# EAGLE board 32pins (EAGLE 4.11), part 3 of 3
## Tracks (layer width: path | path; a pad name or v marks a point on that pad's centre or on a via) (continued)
PUC1\ (continued)
  Top 0.254: SV4.6 184.78,32.86 180.97,32.86 179.7,34.12 167.63,34.12 167,34.76 152.4,34.76 151.12,33.49 151.12,31.59 Q38.G
  Bottom 0.254: Q38.G 151.76,30.95 152.4,30.95 154.3,29.05 155.57,29.05 156.84,27.78 D70.C
PUD1\
  Top 0.254: Q40.G 131.44,30.95 132.08,30.95 133.34,29.68 133.34,27.14 133.98,26.51 135.25,26.51 136.52,27.78 D72.C
  Bottom 0.254: SV4.8 186.05,35.4 187.32,34.12 188.59,34.12 190.5,32.22 190.5,25.87 177.16,12.54 172.08,12.54 170.81,11.27 170.81,8.73 168.91,6.82 130.81,6.82 127,10.63 127,27.14 126.36,27.78 129.53,30.95 130.17,30.95 Q40.G
PUD2\  (via drill 0.61)
  Top 0.254: v144.78,79.84 v140.97,79.84 | D100.C 147.31,71.59 148.59,72.86 148.59,75.4 v146.68,77.3 v151.12,77.3 | v153.66,78.57 178.43,78.57 179.7,79.84 179.7,82.38 185.41,88.1 SV2.4
  Bottom 0.254: v140.97,79.84 140.97,74.77 Q68.G | v144.78,79.84 144.78,79.21 144.14,78.57 145.41,77.3 v146.68,77.3 | v153.66,78.57 152.4,77.3 v151.12,77.3
PUE1\
  Bottom 0.254: Q42.G 161.92,15.71 162.56,15.71 164.46,13.81 165.73,13.81 167,12.54 D74.C 167.63,13.17 168.91,14.44 168.91,16.98 177.8,25.87 185.41,25.87 187.32,27.78 SV4.1
PUE2\
  Top 0.254: Q70.G 131.44,89.37 132.08,89.37 133.34,88.1 133.34,85.56 133.98,84.92 135.25,84.92 136.52,86.19 D102.C 137.79,86.19 139.06,86.19 140.97,84.29 140.97,83.02 141.6,82.38 149.86,82.38 150.49,81.75 166.37,81.75 167,82.38 177.16,82.38 185.41,90.64 SV2.6
PUF1\
  Top 0.254: Q44.G 141.6,15.71 142.24,15.71 143.5,14.44 143.5,11.9 144.14,11.27 145.41,11.27 146.68,12.54 D76.C
  Bottom 0.254: SV4.3 188.59,30.32 189.86,29.05 189.86,26.51 176.53,13.17 171.44,13.17 170.18,11.9 170.18,9.36 168.91,8.09 149.86,8.09 148.59,9.36 148.59,10.63 147.31,11.9 D76.C
PUF2\  (via drill 0.61)
  Top 0.254: Q72.G 141.6,89.37 142.24,89.37 143.5,88.1 143.5,85.56 144.14,84.92 145.41,84.92 146.68,86.19 D104.C | v177.16,81.11 v149.86,81.11
  Bottom 0.254: v177.16,81.11 184.78,81.11 189.22,85.56 189.22,91.91 188.59,92.54 187.32,92.54 186.05,93.81 SV2.8 | v149.86,81.11 148.59,82.38 148.59,84.29 147.31,85.56 D104.C
PUH1\
  Top 0.254: SV4.5 187.32,32.86 186.05,31.59 184.78,31.59 179.7,26.51 169.54,26.51 168.27,27.78 D78.C
  Bottom 0.254: Q46.G 161.92,30.95 162.56,30.95 164.46,29.05 165.73,29.05 167,27.78 D78.C
PUH2\
  Top 0.254: D106.C 156.84,70.95 155.57,69.68 154.3,69.68 153.66,70.32 153.66,72.86 152.4,74.13 151.76,74.13 Q74.G
  Bottom 0.254: SV2.1 187.32,86.19 183.51,82.38 177.16,82.38 169.54,74.77 169.54,70.95 168.27,69.68 164.46,69.68 163.83,69.05 163.83,67.78 163.19,67.14 159.38,67.14 158.75,67.78 158.75,69.05 157.47,70.32 D106.C
PUJ1\  (via drill 0.61)
  Top 0.254: D80.C 146.68,27.78 145.41,26.51 144.14,26.51 143.5,27.14 143.5,29.68 142.24,30.95 141.6,30.95 Q48.G 140.97,30.32 140.97,28.41 139.06,26.51 136.52,26.51 135.88,25.87 135.88,24.6 137.16,23.33 160.02,23.33 162.56,20.79 v167.63,20.79 | v170.18,23.33 179.06,23.33 181.61,25.87 187.96,25.87 189.22,27.14 189.22,33.49 187.96,34.76 SV4.7
  Bottom 0.254: v167.63,20.79 v170.18,23.33
PUJ2\
  Bottom 0.254: Q76.G 161.92,74.13 162.56,74.13 164.46,72.22 165.73,72.22 167,70.95 D108.C 167.63,71.59 168.91,72.86 168.91,75.4 176.53,83.02 177.8,83.02 182.24,87.46 186.05,87.46 187.32,88.73 SV2.3
PUK1\  (via drill 0.61)
  Top 0.254: 135.88,42.38 136.52,43.02 D82.C | 135.88,42.38 135.25,41.74 133.98,41.74 133.34,42.38 133.34,44.92 132.08,46.19 131.44,46.19 Q50.G | v169.54,41.74 172.08,44.29 173.35,44.29 175.89,41.74 186.05,41.74 186.69,41.11 186.69,39.84 185.41,38.57 SV4.10 | v149.86,36.66 146.05,36.66 145.41,37.3 137.16,37.3 135.88,38.57 135.88,42.38
  Bottom 0.254: v169.54,41.74 167,41.74 166.37,41.11 166.37,39.84 168.27,37.94 166.37,36.03 150.49,36.03 v149.86,36.66
PUK2\
  Top 0.254: Q78.G 151.76,89.37 152.4,89.37 153.66,88.1 153.66,85.56 154.3,84.92 155.57,84.92 156.84,86.19 D110.C
  Bottom 0.254: SV2.5 187.32,91.27 186.05,90 175.89,90 167.63,81.75 160.02,81.75 158.75,83.02 158.75,84.29 157.47,85.56 D110.C
PUL1\  (via drill 0.61)
  Top 0.254: Q52.G 151.76,46.19 152.4,46.19 154.3,44.29 155.57,44.29 156.84,43.02 D84.C | v158.11,37.94 165.73,37.94 167,39.2 179.7,39.2 180.97,40.48 184.78,40.48 SV4.12
  Bottom 0.254: v158.11,37.94 156.21,39.84 156.21,41.11 157.47,42.38 D84.C
PUL2\
  Top 0.254: SV2.7 187.32,93.81 186.05,92.54 184.78,92.54 179.7,87.46 169.54,87.46 168.27,86.19 D112.C
  Bottom 0.254: Q80.G 161.92,89.37 162.56,89.37 164.46,87.46 165.73,87.46 167,86.19 D112.C
PUM1\  (via drill 0.61)
  Top 0.254: Q54.G 131.44,61.43 132.08,61.43 133.34,60.16 133.34,57.62 133.98,56.98 135.25,56.98 136.52,58.26 D86.C | v191.77,38.57 188.59,41.74 187.32,41.74 186.05,43.02 SV4.14 | v126.36,29.05 127,29.68 127,57.62 v126.36,58.26
  Bottom 0.254: v191.77,38.57 191.77,29.68 194.94,26.51 171.44,3.01 133.34,3.01 126.36,10 126.36,26.51 125.73,27.14 125.73,28.41 v126.36,29.05 | v126.36,58.26 129.53,61.43 130.17,61.43 Q54.G
PUM2\
  Top 0.254: Q82.G 131.44,104.61 132.08,104.61 133.34,103.34 133.34,100.8 133.98,100.16 135.25,100.16 136.52,101.43 D114.C
  Bottom 0.254: SV2.10 186.05,96.35 187.32,97.62 188.59,97.62 189.86,98.89 189.86,105.24 169.54,125.56 145.41,125.56 144.14,126.83 131.44,126.83 127,122.39 127,112.23 130.81,108.42 130.81,105.24 Q82.G
PUN1\  (via drill 0.61)
  Top 0.254: Q56.G 151.76,61.43 152.4,61.43 153.66,60.16 153.66,57.62 154.3,56.98 155.57,56.98 156.84,58.26 D88.C | v167,64.6 185.41,46.19 SV4.16
  Bottom 0.254: v167,64.6 155.57,64.6 152.4,61.43 151.76,61.43 Q56.G
PUN2\  (via drill 0.61)
  Top 0.254: Q84.G 141.6,104.61 142.24,104.61 143.5,103.34 143.5,100.8 144.14,100.16 145.41,100.16 146.68,101.43 D116.C | v182.24,96.35 184.78,98.89 SV2.12
  Bottom 0.254: v182.24,96.35 180.97,96.35 179.7,95.08 173.35,95.08 168.27,100.16 164.46,100.16 163.83,99.53 163.83,98.26 160.65,95.08 151.76,95.08 148.59,98.26 148.59,99.53 147.31,100.8 D116.C
PUP1\  (via drill 0.61)
  Top 0.254: D90.C 146.68,43.02 145.41,41.74 144.14,41.74 143.5,42.38 143.5,44.92 142.24,46.19 141.6,46.19 Q58.G 140.97,46.83 140.97,48.73 144.78,52.54 158.11,52.54 159.38,51.27 162.56,51.27 v163.83,52.54
  Bottom 0.254: v163.83,52.54 165.09,51.27 168.91,51.27 172.08,48.09 178.43,48.09 184.78,41.74 188.59,41.74 189.22,41.11 189.22,39.84 187.96,38.57 SV4.9
PUP2\  (via drill 0.61)
  Top 0.254: D118.C 136.52,116.67 135.25,115.4 133.98,115.4 133.34,116.04 133.34,118.58 132.08,119.85 131.44,119.85 Q86.G 130.81,120.48 130.81,122.39 130.17,123.02 128.9,123.02 128.27,122.39 v124.45,122.39 | v186.69,110.96 186.69,103.34 185.41,102.07 SV2.14
  Bottom 0.254: v186.69,110.96 170.18,127.47 147.31,127.47 146.05,128.74 130.81,128.74 v124.45,122.39
PUR1\
  Bottom 0.254: Q60.G 161.92,46.19 162.56,46.19 164.46,44.29 165.73,44.29 167,43.02 D92.C 168.27,43.02 169.54,43.02 173.35,39.2 186.05,39.2 187.32,40.48 SV4.11
PUR2\  (via drill 0.61)
  Top 0.254: Q88.G 151.76,119.85 152.4,119.85 153.66,118.58 153.66,116.04 154.3,115.4 155.57,115.4 156.84,116.67 D120.C 157.47,116.04 158.75,114.77 158.75,113.5 159.38,112.86 160.65,112.86 161.28,113.5 161.28,114.77 161.92,115.4 v166.37,115.4 | v173.35,111.59 180.97,103.97 184.78,103.97 SV2.16
  Bottom 0.254: v173.35,111.59 172.08,111.59 168.27,115.4 v166.37,115.4
PUS1\  (via drill 0.61)
  Top 0.254: Q62.G 141.6,61.43 142.24,61.43 143.5,60.16 143.5,57.62 144.14,56.98 145.41,56.98 146.68,58.26 D94.C | v165.09,52.54 163.19,50.63 158.75,50.63 158.11,51.27 v152.4,51.27
  Bottom 0.254: v165.09,52.54 165.73,51.91 169.54,51.91 172.72,48.73 179.06,48.73 183.51,44.29 186.05,44.29 187.32,43.02 SV4.13 | v152.4,51.27 148.59,55.08 148.59,56.35 147.31,57.62 D94.C
PUS2\  (via drill 0.61)
  Top 0.254: Q90.G 151.76,104.61 152.4,104.61 153.66,103.34 153.66,100.8 154.3,100.16 155.57,100.16 156.84,101.43 D122.C | v160.65,96.35 170.18,96.35 171.44,95.08 186.05,95.08 187.32,96.35 SV2.9
  Bottom 0.254: v160.65,96.35 158.75,98.26 158.75,99.53 157.47,100.8 D122.C
PUT2\
  Bottom 0.254: Q92.G 161.92,104.61 162.56,104.61 164.46,102.7 165.73,102.7 167,101.43 D124.C 168.27,101.43 172.08,97.62 186.05,97.62 187.32,98.89 SV2.11
PUU1\
  Bottom 0.254: 166.37,58.89 167,58.26 D96.C | 166.37,58.89 165.73,59.52 164.46,59.52 162.56,61.43 161.92,61.43 Q64.G | 166.37,58.89 166.37,55.08 167.63,53.81 179.06,53.81 187.32,45.55 SV4.15
PUU2\
  Top 0.254: Q94.G 141.6,119.85 142.24,119.85 143.5,118.58 143.5,116.04 144.14,115.4 145.41,115.4 146.68,116.67 D126.C
  Bottom 0.254: SV2.13 187.96,102.07 189.22,103.34 189.22,104.61 170.81,123.02 168.27,123.02 167.63,123.66 146.05,123.66 142.24,119.85 141.6,119.85 Q94.G
PUV1\  (via drill 0.61)
  Top 0.254: v167,65.88 185.41,84.29 185.41,85.56 SV2.2
  Bottom 0.254: 135.88,71.59 136.52,70.95 D98.C | 135.88,71.59 135.25,72.22 133.98,72.22 132.08,74.13 131.44,74.13 Q66.G | v167,65.88 137.79,65.88 135.88,67.78 135.88,71.59
PUV2\  (via drill 0.61)
  Top 0.254: v173.35,116.67 168.27,116.67 D128.C
  Bottom 0.254: Q96.G 161.92,119.85 162.56,119.85 164.46,117.94 165.73,117.94 167,116.67 D128.C | v173.35,116.67 174.62,116.67 187.32,103.97 SV2.15
R1  (via drill 0.61)
  Top 0.254: Q60.D 160.65,44.29 161.92,43.02 163.19,43.02 165.09,44.92 Q59.D | v73.02,37.94 76.83,37.94 77.47,37.3 82.55,37.3 83.81,36.03 101.59,36.03 107.31,41.74 Q16.D 107.95,41.11 v107.95,31.59 | v194.94,105.24 194.94,26.51 172.72,4.28 121.92,4.28 116.84,9.36 116.84,15.71 v125.09,23.96 | v148.59,41.74 146.68,41.74 146.05,41.11 146.05,39.84 145.41,39.2 139.06,39.2 138.43,39.84 v138.43,41.74
  Bottom 0.254: v73.02,37.94 71.75,39.2 62.86,39.2 56.51,45.55 R64.1 | v194.94,105.24 171.44,128.74 167.63,128.74 165.73,130.65 139.06,130.65 133.34,136.36 133.34,137.63 132.08,138.9 SIDE1.26 | v125.09,23.96 125.09,31.59 122.55,34.12 | 122.55,34.12 117.47,34.12 114.93,31.59 v107.95,31.59 | v148.59,41.74 148.59,39.84 149.22,39.2 150.49,39.2 151.12,39.84 151.12,41.11 151.76,41.74 155.57,41.74 156.21,42.38 156.21,43.65 156.84,44.29 159.38,44.29 Q60.D | v138.43,41.74 138.43,38.57 133.98,34.12 122.55,34.12
R2  (via drill 0.61)
  Top 0.254: v80.01,135.09 92.7,122.39 92.7,116.04 93.34,115.4 97.15,115.4 Q30.D | v48.89,129.38 67.31,129.38 73.02,135.09 v76.2,135.09 | v130.81,116.04 130.81,113.5 131.44,112.86 135.25,112.86 135.88,113.5 135.88,114.77 136.52,115.4 140.33,115.4 140.97,114.77 140.97,113.5 141.6,112.86 145.41,112.86 146.05,113.5 146.05,114.77 146.68,115.4 147.95,115.4 149.86,117.31 Q88.D | v128.9,119.85 118.74,119.85 v116.2,122.39 | v109.85,129.38 v106.04,129.38
  Bottom 0.254: Q88.D 150.49,117.94 151.76,116.67 153.03,116.67 154.94,118.58 Q87.D | v80.01,135.09 78.73,135.09 77.47,136.36 | 77.47,136.36 77.47,137.63 76.83,138.27 | 76.83,138.27 76.2,138.9 SIDE2.26 | v48.89,129.38 45.08,125.56 29.84,125.56 26.03,121.75 R120.1 | 77.47,136.36 v76.2,135.09 | v130.81,116.04 129.53,116.04 128.27,117.31 128.27,119.21 v128.9,119.85 | v116.2,122.39 109.85,128.74 v109.85,129.38 | v106.04,129.38 93.98,141.44 83.81,141.44 82.55,140.17 82.55,138.9 81.91,138.27 76.83,138.27
RXA1  (via drill 0.61)
  Top 0.254: R7.1 17.78,11.9 19.68,10 D2.C 20.95,10 v25.39,5.55 | v58.41,19.52 60.95,16.98 60.95,13.17 54.6,6.82 43.17,6.82 v41.9,5.55
  Bottom 0.254: v58.41,19.52 58.41,22.06 63.49,27.14 SV7.2 | v25.39,5.55 v41.9,5.55
RXB1  (via drill 0.61)
  Top 0.254: v52.7,3.65 v62.22,13.17
  Bottom 0.254: R18.1 15.23,11.9 15.23,10.63 D9.C 15.23,9.36 17.78,6.82 49.52,6.82 v52.7,3.65 | v62.22,13.17 56.51,18.89 56.51,23.96 62.86,30.32 SV7.4
RXC1  (via drill 0.61)
  Top 0.254: v68.58,5.55 69.84,4.28 67.94,2.38 43.81,2.38 36.82,9.36 36.82,10.63 36.19,11.27 32.38,11.27 31.75,11.9 31.75,18.89 27.3,23.33 22.22,23.33 21.59,23.96 21.59,28.41 20.95,29.05 v19.05,29.05
  Bottom 0.254: D10.C 15.23,32.22 15.23,30.95 R22.1 15.87,30.32 17.14,29.05 v19.05,29.05 | v68.58,5.55 68.58,18.89 66.04,21.43 62.86,18.25 58.41,18.25 57.14,19.52 57.14,23.33 62.86,29.05 64.13,29.05 64.77,29.68 64.77,30.95 63.49,32.22 SV7.6
RXD1  (via drill 0.61)
  Top 0.254: v57.78,15.08 57.78,12.54 53.97,8.73 v45.08,8.73 | v16.51,22.06 16.51,28.41 17.78,29.68 R26.1
  Bottom 0.254: R26.1 18.41,30.32 20.32,32.22 D11.C | v57.78,15.08 55.24,17.62 55.24,25.23 55.88,25.87 55.88,28.41 62.86,35.4 SV7.8 | v45.08,8.73 43.81,7.46 18.41,7.46 16.51,9.36 v16.51,22.06
RXD2  (via drill 0.61)
  Top 0.254: D25.C 15.23,69.05 15.23,70.32 R82.1 | v57.78,66.51 v62.22,70.95 | v36.82,66.51 36.82,71.59 36.19,72.22 34.92,72.22 34.28,71.59 34.28,70.32 30.48,66.51 v19.05,66.51
  Bottom 0.254: v62.22,70.95 69.21,77.94 69.21,87.46 66.67,90 65.4,90 64.13,88.73 SV8.4 | v57.78,66.51 57.78,65.88 56.51,64.6 55.24,64.6 53.34,66.51 v36.82,66.51 | v19.05,66.51 17.78,66.51 15.87,68.41 D25.C
RXE1  (via drill 0.61)
  Top 0.254: D12.C 42.54,10 40.63,11.9 R30.1 | v56.51,17.62 54.6,19.52 47.62,19.52 46.98,18.89 46.35,19.52 42.54,19.52 41.9,18.89 v40.63,20.16
  Bottom 0.254: v56.51,17.62 55.88,18.25 55.88,24.6 56.51,25.23 56.51,27.78 62.86,34.12 66.67,34.12 67.31,33.49 67.31,29.68 66.04,28.41 SV7.1 | v40.63,20.16 39.36,18.89 39.36,14.44 40.63,13.17 R30.1
RXE2  (via drill 0.61)
  Top 0.254: v56.51,84.92 62.86,91.27 SV8.6 | v56.51,80.48 22.22,80.48 v21.59,81.11 | v19.05,81.11 17.78,81.11 16.51,82.38 16.51,86.83 15.23,88.1 R86.1
  Bottom 0.254: R86.1 15.23,89.37 15.23,90.64 D26.C | v56.51,80.48 v56.51,84.92 | v19.05,81.11 v21.59,81.11
RXF1  (via drill 0.61)
  Top 0.254: R34.1 38.09,11.9 38.09,10.63 D13.C 38.73,10 41.27,7.46 53.97,7.46 59.68,13.17 v59.68,16.98 | v66.04,20.16 v62.22,23.96
  Bottom 0.254: v62.22,23.96 64.77,26.51 64.77,28.41 66.04,29.68 SV7.3 | v66.04,20.16 62.86,16.98 v59.68,16.98
RXF2
  Top 0.254: SV8.8 62.86,93.81 41.27,93.81 36.82,98.26 36.82,99.53 36.19,100.16 34.92,100.16 34.28,99.53 34.28,93.81 33.02,92.54 27.3,92.54 26.67,91.91 26.67,90.64 26.03,90 22.22,90 20.95,91.27 D27.C
  Bottom 0.254: R90.1 18.41,88.73 20.32,90.64 D27.C
RXH1
  Top 0.254: SV7.5 65.4,32.86 64.13,34.12 55.24,34.12 50.16,39.2 45.08,39.2 38.73,32.86 D14.C
  Bottom 0.254: R38.1 38.09,30.95 38.09,32.22 D14.C
RXH2  (via drill 0.61)
  Top 0.254: 41.9,69.05 40.63,70.32 R94.1 | 41.9,69.05 42.54,68.41 D28.C | v63.49,77.3 54.6,77.3 53.97,77.94 42.54,77.94 41.9,77.3 41.9,69.05
  Bottom 0.254: v63.49,77.3 65.4,77.3 67.94,79.84 66.04,81.75 66.04,85.56 SV8.1
RXJ1  (via drill 0.61)
  Top 0.254: v53.97,36.66 64.13,36.66 65.4,35.4 SV7.7 | v44.45,36.03 44.45,34.76 43.17,33.49 D15.C
  Bottom 0.254: R42.1 41.27,30.32 43.17,32.22 D15.C | v53.97,36.66 52.7,36.66 51.43,35.4 45.08,35.4 v44.45,36.03
RXJ2  (via drill 0.61)
  Top 0.254: D29.C 38.09,69.05 38.09,70.32 R98.1 38.09,71.59 39.36,72.86 39.36,77.3 40.63,78.57 63.49,78.57 64.13,77.94 v67.31,77.94
  Bottom 0.254: v67.31,77.94 68.58,79.21 68.58,85.56 66.04,88.1 SV8.3
RXK1  (via drill 0.61)
  Top 0.254: R46.1 17.78,42.38 19.68,40.48 D16.C | v22.86,38.57 v27.94,38.57
  Bottom 0.254: v27.94,38.57 31.11,35.4 38.73,35.4 40.63,37.3 44.45,37.3 45.71,36.03 50.79,36.03 52.7,37.94 62.86,37.94 SV7.10 | v22.86,38.57 20.95,40.48 D16.C
RXK2  (via drill 0.61)
  Top 0.254: R102.1 38.09,89.37 38.09,90.64 D30.C | v41.9,92.54 64.13,92.54 65.4,91.27 SV8.5
  Bottom 0.254: v41.9,92.54 40,92.54 38.73,91.27 D30.C
RXL1  (via drill 0.61)
  Top 0.254: D17.C 15.23,41.11 15.23,42.38 R50.1 | v70.48,45.55 65.4,50.63 24.76,50.63 22.86,52.54 v19.68,52.54
  Bottom 0.254: v70.48,45.55 66.67,41.74 65.4,41.74 64.13,40.48 SV7.12 | v19.68,52.54 16.51,49.37 16.51,44.92 15.23,43.65 R50.1
RXL2
  Bottom 0.254: R106.1 41.27,88.73 43.17,90.64 D31.C 43.81,91.27 45.08,92.54 64.13,92.54 65.4,93.81 SV8.7
RXM1  (via drill 0.61)
  Top 0.254: D18.C 15.23,62.7 15.23,61.43 R54.1 14.6,60.8 13.33,59.52 12.06,59.52 11.42,58.89 11.42,56.98 18.41,50 v24.12,50
  Bottom 0.254: v24.12,50 24.76,50.63 53.34,50.63 60.95,43.02 62.86,43.02 SV7.14
RXM2  (via drill 0.61)
  Top 0.254: R110.1 17.78,100.8 19.68,98.89 D32.C | v22.86,97.62 v29.21,97.62
  Bottom 0.254: v29.21,97.62 30.48,96.35 62.86,96.35 SV8.10 | v22.86,97.62 21.59,98.89 20.95,98.89 D32.C
RXN1  (via drill 0.61)
  Top 0.254: v22.22,51.27 19.68,51.27 16.51,54.45 16.51,58.89 17.78,60.16 R58.1
  Bottom 0.254: R58.1 18.41,60.8 20.32,62.7 D19.C | v22.22,51.27 53.97,51.27 59.68,45.55 62.86,45.55 SV7.16
RXN2  (via drill 0.61)
  Top 0.254: D33.C 15.23,99.53 15.23,100.8 R114.1 | v46.35,97.62 52.7,97.62 53.97,98.89 62.86,98.89 SV8.12 | v27.3,94.45 v31.75,98.89
  Bottom 0.254: v46.35,97.62 33.02,97.62 v31.75,98.89 | v27.3,94.45 19.05,94.45 15.23,98.26 D33.C
RXP1  (via drill 0.61)
  Top 0.254: R62.1 40.63,42.38 42.54,40.48 D20.C | v67.31,26.51 67.31,36.03 66.04,37.3 SV7.9 | v59.68,20.16 59.05,20.16 58.41,20.79 47.62,20.79 v46.98,20.16 | v45.71,21.43 44.45,20.16 v41.9,20.16 | v33.02,32.86 v33.02,36.66
  Bottom 0.254: v67.31,26.51 66.04,26.51 v59.68,20.16 | v45.71,21.43 v46.98,20.16 | v41.9,20.16 41.9,20.79 39.36,23.33 37.46,23.33 33.02,27.78 v33.02,32.86 | v33.02,36.66 38.73,36.66 42.54,40.48 D20.C
RXP2  (via drill 0.61)
  Top 0.254: v69.21,123.66 v69.21,102.7 | v69.21,129.38 68.58,129.38 67.94,128.74 61.59,128.74 60.32,127.47 43.17,127.47 v39.36,131.28 | v15.23,128.74 v17.78,131.28
  Bottom 0.254: R118.1 15.23,119.85 15.23,121.12 D34.C 15.23,122.39 v15.23,128.74 | v69.21,102.7 65.4,102.7 64.13,101.43 SV8.14 | v69.21,129.38 v69.21,123.66 | v17.78,131.28 v39.36,131.28
RXR1  (via drill 0.61)
  Top 0.254: D21.C 38.09,41.11 38.09,42.38 R66.1 | v52.06,38.57 55.24,41.74 64.13,41.74 65.4,40.48 SV7.11
  Bottom 0.254: v52.06,38.57 48.25,38.57 46.35,36.66 44.45,38.57 44.45,41.11 43.81,41.74 40,41.74 38.73,43.02 R66.1
RXR2  (via drill 0.61)
  Top 0.254: v63.49,115.4 54.6,124.29 45.08,124.29 v42.54,126.83
  Bottom 0.254: R122.1 18.41,119.21 20.32,121.12 D35.C 20.95,121.75 26.03,126.83 v42.54,126.83 | v63.49,115.4 63.49,104.61 SV8.16
RXS1
  Top 0.254: R70.1 38.09,61.43 38.09,62.7 D22.C
  Bottom 0.254: SV7.13 66.04,43.65 64.77,44.92 64.77,46.19 57.14,53.81 42.54,53.81 41.9,54.45 41.9,58.89 41.27,59.52 40,59.52 38.73,60.8 R70.1
RXS2
  Top 0.254: 40.63,100.8 42.54,98.89 D36.C | 40.63,100.8 R126.1 40.63,100.8 | 40.63,100.8 39.36,99.53 39.36,98.26 42.54,95.08 64.13,95.08 65.4,96.35 SV8.9
RXT2
  Top 0.254: D37.C 38.09,99.53 38.09,100.8 R130.1
  Bottom 0.254: SV8.11 65.4,98.89 64.13,100.16 62.22,100.16 52.06,110.32 40.63,110.32 39.36,109.05 39.36,103.34 38.09,102.07 R130.1
RXU1  (via drill 0.61)
  Top 0.254: v55.88,56.35 55.88,62.7 53.97,64.6 45.08,64.6 43.81,63.34 D23.C
  Bottom 0.254: R74.1 41.27,60.8 43.17,62.7 D23.C | v55.88,56.35 66.04,46.19 SV7.15
RXU2  (via drill 0.61)
  Top 0.254: R134.1 38.09,119.85 38.09,121.12 D38.C | v44.45,123.66 53.97,123.66 67.31,110.32 67.31,103.34 66.04,102.07 SV8.13
  Bottom 0.254: v44.45,123.66 40.63,123.66 38.73,121.75 D38.C
RXV1  (via drill 0.61)
  Top 0.254: D24.C 19.68,68.41 17.78,70.32 R78.1 | v75.56,95.08 67.94,87.46 65.4,87.46 64.13,86.19 SV8.2 | v34.28,105.88 34.28,100.8 33.02,99.53 v33.02,93.81
  Bottom 0.254: v75.56,95.08 79.37,98.89 79.37,103.97 77.47,105.88 77.47,107.15 64.77,119.85 61.59,119.85 53.97,112.23 40.63,112.23 v34.28,105.88 | v33.02,93.81 33.02,83.65 27.94,78.57 20.32,78.57 19.05,77.3 19.05,72.86 17.78,71.59 R78.1
RXV2  (via drill 0.61)
  Top 0.254: v62.86,118.58 62.86,123.66 v61.59,124.93
  Bottom 0.254: R138.1 41.27,119.21 43.17,121.12 D39.C 43.81,121.75 53.97,131.92 55.24,131.92 56.51,130.65 56.51,130.01 v61.59,124.93 | v62.86,118.58 62.22,117.94 62.22,103.34 62.86,102.7 64.13,102.7 65.4,103.97 SV8.15
S1  (via drill 0.61)
  Top 0.254: 82.55,62.06 82.55,63.97 81.91,64.6 78.1,64.6 77.47,63.97 77.47,62.7 76.83,62.06 v64.77,62.06 | 82.55,62.06 82.55,57.62 83.18,56.98 86.99,56.98 Q17.D | v168.91,130.01 168.91,124.93 180.97,112.86 v180.97,105.24 | v186.69,100.16 188.59,100.16 191.77,96.99 191.77,51.27 186.69,46.19 186.69,44.92 186.05,44.29 178.43,44.29 177.8,44.92 177.8,50 170.18,57.62 168.91,57.62 168.27,56.98 161.92,56.98 161.28,56.35 161.28,55.08 160.65,54.45 159.38,54.45 158.75,55.08 158.75,56.35 158.11,56.98 156.84,56.98 156.21,56.35 156.21,55.08 155.57,54.45 149.22,54.45 148.59,55.08 148.59,56.35 147.95,56.98 146.68,56.98 146.05,56.35 146.05,55.08 145.41,54.45 141.6,54.45 140.97,55.08 140.97,57.62 139.69,58.89 Q62.D | v87.62,62.06 82.55,62.06 | v119.38,61.43 v116.2,64.6
  Bottom 0.254: v64.77,62.06 63.49,62.06 62.22,63.34 53.97,63.34 R68.1 | 140.97,58.89 141.6,58.26 142.87,58.26 144.78,60.16 Q61.D | 140.97,58.89 140.33,59.52 Q62.D | v168.91,130.01 160.65,138.27 141.6,138.27 140.33,139.53 SIDE1.32 | v180.97,105.24 180.97,103.97 184.78,100.16 v186.69,100.16 | v87.62,62.06 102.23,62.06 102.87,61.43 102.87,60.16 103.5,59.52 106.04,59.52 108.58,62.06 113.66,62.06 v116.2,64.6 | v119.38,61.43 119.38,56.35 121.92,53.81 126.36,53.81 127.63,52.54 138.43,52.54 140.97,55.08 140.97,58.89
S2  (via drill 0.61)
  Top 0.254: 84.45,97.62 86.99,100.16 Q31.D | 84.45,97.62 82.55,95.72 80.01,95.72 79.37,96.35 73.02,96.35 v71.75,97.62 71.12,98.26 71.12,108.42 71.75,109.05 v71.75,120.48 | v146.68,107.78 139.06,107.78 138.43,108.42 132.08,108.42 125.09,115.4 v122.55,112.86 | v114.93,119.21 113.66,119.21 112.39,120.48 111.12,120.48 109.22,118.58 109.22,108.42 107.95,107.15 107.95,105.88 107.31,105.24 103.5,105.24 102.87,104.61 102.87,98.26 102.23,97.62 84.45,97.62
  Bottom 0.254: Q89.D 154.94,103.34 153.03,101.43 151.76,101.43 150.49,102.7 Q90.D 149.86,103.34 149.86,104.61 v146.68,107.78 | v71.75,97.62 50.16,97.62 48.89,98.89 R124.1 | v71.75,120.48 72.39,121.12 72.39,140.17 73.02,140.81 76.83,140.81 78.1,139.53 SIDE2.28 | v122.55,112.86 121.28,112.86 v114.93,119.21
T1
  Top 0.254: SIDE1.34 142.24,140.17 142.24,145.89 T1.1
T2  (via drill 0.61)
  Top 0.254: 55.88,108.42 v55.88,120.48 | 55.88,108.42 55.88,104.61 R128.1 | v55.24,130.65 59.68,130.65 64.13,135.09 v68.58,135.09 | v115.56,103.34 115.56,109.69 123.19,117.31 124.45,117.31 132.71,109.05 v156.84,109.05 | Q91.D 165.09,103.34 163.19,101.43 161.92,101.43 160.65,102.7 Q92.D | v66.04,108.42 55.88,108.42 | v72.39,108.42 72.39,98.26 73.66,96.99 v80.01,96.99 | v82.55,94.45 104.14,94.45 107.95,98.26 107.95,99.53 Q32.D
  Bottom 0.254: v55.88,120.48 47.62,120.48 46.98,121.12 46.98,122.39 v55.24,130.65 | v68.58,135.09 69.84,136.36 69.84,140.17 71.12,141.44 78.73,141.44 80.64,139.53 SIDE2.30 | v115.56,103.34 112.39,100.16 108.58,100.16 Q32.D | v156.84,109.05 156.84,107.15 160.02,103.97 160.02,103.34 Q92.D | v72.39,108.42 v66.04,108.42 | v82.55,94.45 v80.01,96.99
THR  (via drill 0.61)
  Top 0.254: 24.12,120.48 24.12,119.21 JP29.2 | 24.12,120.48 24.12,122.39 20.32,126.2 20.32,143.98 THR.2 20.95,144.62 33.02,144.62 36.82,140.81 36.82,130.01 44.45,122.39 44.45,121.12 45.08,120.48 46.35,120.48 46.98,119.85 46.98,119.21 JP33.2 | 24.12,120.48 28.57,120.48 29.21,119.85 29.21,119.21 JP28.2 | v40.63,109.05 33.65,109.05 v31.75,110.96 | v46.35,37.94 46.35,34.12 46.98,33.49 46.98,30.32 JP9.2 | JP1.2 24.12,12.54 24.12,13.17 24.76,13.81 26.67,13.81 27.3,13.17 JP3.2 | v60.32,60.8 55.88,65.24 THR_TP.1 | JP21.2 24.76,88.1 24.12,88.1 23.49,87.46 22.22,87.46 21.59,86.83 21.59,82.38 19.05,79.84 19.05,72.86 19.68,72.22 21.59,72.22 22.22,71.59 JP18.2
  Bottom 0.254: JP21.2 26.67,88.73 26.67,89.37 27.3,90 29.21,90 29.84,89.37 JP20.2 31.11,89.37 31.11,90 31.75,90.64 31.75,91.91 26.03,97.62 24.76,97.62 24.12,98.26 24.12,100.8 | 24.12,100.8 23.49,100.8 JP26.2 21.59,101.43 21.59,102.07 20.95,102.7 19.68,102.7 19.05,103.34 19.05,107.78 22.22,110.96 v31.75,110.96 31.75,115.4 32.38,116.04 32.38,117.31 31.11,118.58 JP28.2 | 24.12,100.8 24.76,100.16 26.67,100.16 27.3,100.8 JP27.2 | JP33.2 48.89,118.58 49.52,118.58 50.16,117.94 52.06,117.94 52.7,118.58 JP32.2 | JP31.2 50.16,100.8 49.52,100.16 47.62,100.16 46.98,100.8 46.35,100.8 JP30.2 44.45,101.43 44.45,102.07 43.81,102.7 42.54,102.7 41.9,103.34 41.9,107.78 v40.63,109.05 | JP14.2 46.98,43.02 46.98,43.65 47.62,44.29 49.52,44.29 50.16,43.65 JP15.2 | JP9.2 48.89,29.68 49.52,29.68 50.16,29.05 52.06,29.05 52.7,29.68 JP8.2 53.97,29.68 55.24,28.41 55.24,26.51 54.6,25.87 54.6,14.44 53.97,13.81 52.06,13.81 51.43,13.17 JP7.2 50.16,11.9 49.52,11.27 47.62,11.27 46.98,11.9 | v46.35,37.94 46.35,42.38 JP14.2 | 46.98,11.9 46.35,11.9 JP6.2 | 46.98,11.9 43.81,8.73 27.3,8.73 26.67,9.36 26.67,10.63 27.3,11.27 27.3,11.9 JP3.2 | JP25.2 48.89,88.1 49.52,88.1 50.16,87.46 52.06,87.46 52.7,88.1 JP24.2 53.97,88.1 55.24,86.83 55.24,74.77 54.6,74.13 54.6,66.51 | JP22.2 46.35,70.32 46.98,70.32 47.62,69.68 49.52,69.68 50.16,70.32 JP23.2 50.79,70.32 54.6,66.51 | 54.6,66.51 55.24,65.88 THR_TP.1 | 24.12,42.38 23.49,42.38 JP10.2 21.59,43.02 21.59,43.65 20.95,44.29 19.68,44.29 19.05,44.92 19.05,49.37 23.49,53.81 31.11,53.81 32.38,55.08 32.38,58.89 31.11,60.16 JP12.2 29.84,60.16 29.21,60.16 28.57,59.52 26.67,59.52 26.03,60.16 JP13.2 24.12,60.8 24.12,64.6
  Bottom 0.254: 24.12,42.38 24.76,41.74 26.67,41.74 27.3,42.38 JP11.2 28.57,42.38 31.75,39.2 36.19,39.2 36.82,39.84 36.82,49.37 37.46,50 41.27,50 41.9,49.37 41.9,44.92 42.54,44.29 43.81,44.29 44.45,43.65 44.45,43.02 JP14.2 | 24.76,31.59 24.76,30.95 JP5.2 | 24.76,31.59 24.12,32.22 24.12,42.38 | 24.76,31.59 28.57,31.59 29.21,30.95 29.21,30.32 JP4.2 | 24.12,64.6 24.12,68.41 23.49,69.05 23.49,70.32 JP18.2 23.49,71.59 24.12,72.22 26.03,72.22 26.67,71.59 26.67,70.95 JP19.2 | 24.12,64.6 46.35,64.6 46.98,63.97 46.98,62.7 47.62,62.06 47.62,61.43 JP17.2 48.89,60.16 49.52,60.16 50.16,59.52 52.06,59.52 52.7,60.16 JP16.2 54.6,60.8 v60.32,60.8
U1  (via drill 0.61)
  Top 0.254: Q64.D 160.65,59.52 161.92,58.26 163.19,58.26 165.09,60.16 Q63.D | v130.81,127.47 129.53,127.47 128.27,128.74 128.27,131.28 124.45,135.09 v116.84,135.09 101.59,135.09 100.33,136.36 100.33,140.17 100.96,140.81 102.23,140.81 103.5,139.53 SIDE1.4 | v190.5,85.56 v168.91,63.97 | v120.65,56.35 v114.93,50.63 | v128.9,57.62 128.9,58.26 128.27,58.89 128.27,107.78 v128.9,108.42
  Bottom 0.254: 106.04,56.98 99.69,56.98 95.88,53.18 74.29,53.18 73.66,52.54 71.75,52.54 62.22,62.06 50.16,62.06 48.89,63.34 R72.1 | 106.04,56.98 107.31,56.98 Q18.D | v130.81,127.47 146.05,127.47 147.31,126.2 170.18,126.2 190.5,105.88 v190.5,85.56 | v168.91,63.97 168.91,60.16 168.27,59.52 167,59.52 165.73,60.8 Q63.D | 106.04,56.98 106.04,54.45 107.31,53.18 111.12,53.18 111.76,53.81 v114.93,50.63 | v120.65,56.35 127.63,56.35 v128.9,57.62 | v128.9,108.42 128.27,108.42 117.47,119.21 117.47,134.46 v116.84,135.09
U2  (via drill 0.61)
  Top 0.254: 82.55,126.2 86.36,126.2 90.17,122.39 90.17,118.58 87.62,116.04 Q33.D | 82.55,126.2 v67.94,126.2 | v82.55,131.28 82.55,126.2 | v137.79,121.12 135.25,123.66 114.3,123.66 113.03,124.93 v104.14,124.93
  Bottom 0.254: Q93.D 144.78,118.58 142.87,116.67 141.6,116.67 140.33,117.94 Q94.D 139.69,118.58 137.79,120.48 v137.79,121.12 | v67.94,126.2 63.49,121.75 53.97,121.75 R132.1 | 85.09,135.09 85.09,133.82 v82.55,131.28 | 85.09,135.09 85.09,137.63 86.36,138.9 SIDE2.34 | v104.14,124.93 102.87,126.2 102.87,127.47 104.14,128.74 97.79,135.09 85.09,135.09
V1  (via drill 0.61)
  Top 0.254: Q66.D 130.17,72.22 131.44,70.95 132.71,70.95 134.62,72.86 Q65.D | v19.05,136.36 19.05,133.82 9.52,124.29 9.52,69.68 12.69,66.51 v15.23,66.51 | v22.86,68.41 R76.1 | v125.73,86.19 125.73,107.15 125.09,107.78 v125.09,114.13 | v129.53,126.2 133.34,126.2 143.5,136.36 143.5,137.63 142.87,138.27 139.06,138.27 138.43,138.9 138.43,140.17 137.79,140.81 111.12,140.81 110.48,140.17 110.48,138.9 109.85,138.27 103.5,138.27 102.23,139.53 SIDE1.2
  Bottom 0.254: Q19.D 76.83,69.68 66.67,69.68 60.95,63.97 54.6,63.97 53.34,65.24 33.02,65.24 28.57,69.68 26.03,69.68 25.39,70.32 R76.1 | v19.05,136.36 26.67,143.98 44.45,143.98 45.71,142.71 95.25,142.71 98.42,139.53 100.96,139.53 SIDE1.2 | v15.23,66.51 16.51,66.51 17.78,65.24 19.68,65.24 v22.86,68.41 | v125.73,86.19 124.45,84.92 124.45,77.94 129.53,72.86 Q66.D | v125.09,114.13 125.09,121.75 v129.53,126.2
V2  (via drill 0.61)
  Top 0.254: Q96.D 160.65,117.94 161.92,116.67 163.19,116.67 165.09,118.58 Q95.D | v65.4,126.2 66.67,127.47 73.66,127.47 78.73,132.55 | v80.01,133.82 78.73,132.55 | 78.73,132.55 78.73,135.09 80.01,136.36 84.45,131.92 93.34,131.92 102.87,122.39 102.87,116.04 103.5,115.4 107.31,115.4 Q34.D | v158.11,121.12 154.94,124.29 121.28,124.29 118.11,127.47 101.59,127.47 v89.53,139.53
  Bottom 0.254: v65.4,126.2 61.59,122.39 60.95,123.02 50.16,123.02 48.89,121.75 R136.1 | v80.01,133.82 82.55,136.36 82.55,137.63 83.81,138.9 SIDE2.32 84.45,139.53 85.72,140.81 86.99,140.81 88.26,139.53 v89.53,139.53 | v158.11,121.12 158.11,120.48 160.02,118.58 Q96.D
V+  (via drill 0.61)
  Top 0.254: IC1.3 20.32,16.35 20.32,15.71 R6.2 19.68,15.08 18.41,13.81 14.6,13.81 13.33,12.54 R17.2 12.69,13.17 11.42,14.44 11.42,28.41 12.69,29.68 R21.2 13.33,30.32 14.6,31.59 18.41,31.59 19.68,30.32 R25.2 | 16.51,44.29 18.41,44.29 19.68,45.55 R45.2 20.32,46.19 20.32,46.83 IC3.3 | 16.51,44.29 14.6,44.29 13.33,43.02 R49.2 | R33.2 36.19,12.54 37.46,13.81 41.27,13.81 42.54,15.08 R29.2 43.17,15.71 43.17,16.35 IC2.3 | R41.2 42.54,30.32 41.27,29.05 37.46,29.05 36.19,30.32 R37.2 35.55,30.95 34.28,32.22 34.28,41.11 35.55,42.38 R65.2 36.19,43.02 37.46,44.29 41.27,44.29 42.54,45.55 R61.2 43.17,46.19 43.17,46.83 IC4.3 | 16.51,120.48 18.41,120.48 19.68,119.21 R121.2 | 16.51,120.48 14.6,120.48 13.33,119.21 R117.2 | R89.2 19.68,88.73 18.41,90 14.6,90 13.33,88.73 R85.2 12.69,88.1 11.42,86.83 11.42,72.86 12.69,71.59 R81.2 | R113.2 13.33,101.43 14.6,102.7 18.41,102.7 19.68,103.97 R109.2 20.32,104.61 20.32,105.24 IC7.3 | 16.51,120.48 16.51,111.59 20.32,107.78 IC7.3 | R77.2 20.32,74.13 20.32,74.77 IC5.3 | R73.2 42.54,60.8 41.27,59.52 37.46,59.52 36.19,60.8 R69.2 35.55,61.43 34.28,62.7 34.28,69.05 35.55,70.32 R97.2 | R93.2 43.17,74.13 43.17,74.77 IC6.3 | R101.2 36.19,88.73 37.46,87.46 41.27,87.46 42.54,88.73 R105.2 | 16.51,44.29 16.51,50.63 v13.96,53.18 | 39.36,102.7 41.27,102.7 42.54,103.97 R125.2 43.17,104.61 43.17,105.24 IC8.3 43.17,107.78 43.17,111.59 44.45,112.86 44.45,117.31 43.17,118.58 R137.2 42.54,119.21 41.27,117.94 37.46,117.94 36.19,119.21 R133.2 34.92,119.21 32.38,121.75 32.38,139.53 | 39.36,102.7 37.46,102.7 36.19,101.43 R129.2 | 5V.2 195.58,123.02 193.03,125.56 IC9.IN 193.03,128.11 188.59,128.11
  Top 0.254: 32.38,139.53 34.92,139.53 A2.2 | 32.38,139.53 31.11,139.53 R323.2 | 188.59,128.11 188.59,143.98 188.59,146.52 185.41,149.7 120.01,149.7 116.84,146.52 91.44,146.52 88.9,149.06 47.62,149.06 46.98,148.43 46.98,145.89 v42.54,141.44 | 39.36,102.7 39.36,107.78 38.73,108.42 22.22,108.42 20.95,107.15 IC7.3 | 188.59,128.11 177.8,128.11 175.25,130.65 V+.1
  Bottom 0.254: R21.2 12.69,30.95 11.42,32.22 11.42,41.11 12.69,42.38 R49.2 | IC2.3 43.17,18.89 43.17,22.7 41.9,23.96 41.9,28.41 43.17,29.68 R41.2 | IC1.3 20.95,18.25 22.22,19.52 31.11,19.52 34.28,16.35 34.28,14.44 35.55,13.17 R33.2 | R85.2 12.69,89.37 11.42,90.64 11.42,99.53 12.69,100.8 R113.2 | 13.96,60.16 14.6,59.52 18.41,59.52 19.68,60.8 R57.2 | 13.96,60.16 13.33,60.8 R53.2 | 13.33,69.68 13.96,69.05 13.96,60.16 | 13.33,69.68 12.69,70.32 R81.2 | 13.33,69.68 18.41,69.68 19.05,70.32 19.05,71.59 20.32,72.86 R77.2 | R105.2 43.17,88.1 44.45,86.83 44.45,82.38 43.17,81.11 43.17,77.3 IC6.3 | 34.28,77.94 34.28,86.83 35.55,88.1 R101.2 | 34.28,77.94 34.28,72.86 35.55,71.59 R97.2 | 34.28,77.94 22.22,77.94 20.95,76.67 IC5.3 | 13.96,60.16 v13.96,53.18 | v42.54,141.44 37.46,141.44 36.19,140.17 A2.2
V-  (via drill 0.61)
  Top 0.254: v40,21.43 v44.45,21.43 | v40.63,53.18 42.54,55.08 IC4.12 | v24.12,52.54 22.86,53.81 22.22,53.81 20.95,55.08 IC3.12 | v24.12,112.23 41.27,112.23 42.54,113.5 IC8.12 | v24.12,81.75 v35.55,81.75
  Bottom 0.254: 11.42,46.83 19.68,55.08 IC3.12 | 11.42,46.83 10.79,46.19 10.79,27.14 14.6,23.33 18.41,23.33 19.68,24.6 IC1.12 20.95,24.6 24.12,21.43 v40,21.43 | 16.51,79.84 11.42,74.77 11.42,46.83 | 16.51,79.84 19.68,83.02 IC5.12 20.95,83.02 22.22,81.75 v24.12,81.75 | 17.78,111.59 10.79,104.61 10.79,85.56 16.51,79.84 | 17.78,111.59 18.41,112.23 | 18.41,112.23 19.68,113.5 IC7.12 | v44.45,21.43 44.45,22.7 43.17,23.96 IC2.12 | v40.63,53.18 39.36,51.91 24.76,51.91 v24.12,52.54 | 18.41,112.23 v24.12,112.23 | 17.78,111.59 16.51,112.86 16.51,137.63 17.78,138.9 R321.1 18.41,139.53 20.32,139.53 31.11,150.33 42.54,150.33 45.08,147.79 B2.2 46.35,146.52 49.52,143.34 109.85,143.34 116.2,149.7 180.34,149.7 182.24,147.79 IC10.IN 182.24,146.52 180.34,144.62 175.89,144.62 V-.1 | v35.55,81.75 41.27,81.75 42.54,83.02 IC6.12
